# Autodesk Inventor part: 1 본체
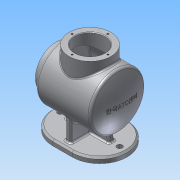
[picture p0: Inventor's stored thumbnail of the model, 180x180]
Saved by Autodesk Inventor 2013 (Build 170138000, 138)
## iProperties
Created: 2016-04
Part Number: 1 본체
Material: 알루미늄 6061
Document SubType Name: Modeling
Designer: Administrator
Mass: 911.528 g
Surface Area: 1226.33 cm^2
Volume: 336.357 cm^3
Density: 2.71 g/cm^3
Author: Administrator
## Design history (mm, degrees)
sketch "스케치1"
  geometry: L1 (-17.5, 50)-(17.5, 50); L2 (17.5, -50)-(-17.5, -50); A1 r 50 centre (17.5, 0) between (17.5, -50) and (17.5, 50); A2 r 50 centre (-17.5, 0) between (-17.5, 50) and (-17.5, -50); 2 further points
  constraints: 4 end point, 4 point on circle, 4 tangent, 2 centre point, 2 horizontal, 2 horizontal alignment, 1 midpoint, 1 vertical alignment
  dimensions: "d0" = 100 distance between parallel lines of L1 L2; "d2" = 135 dimension on A2 A1
extrude "돌출1" new body sketch "스케치1" distance "d3" = 10; taper "d4" = 0 deg
sketch "스케치3"
  geometry: L1 (67.5, 0)-(67.5, 10) reference; L2 (-67.5, 0)-(-67.5, 10) reference; L3 (-97.541, 79)-(111.394, 79); L4 (61.544, 79)-(61.544, 117); L5 (61.544, 117)-(49.544, 117); L6 (49.544, 117)-(49.544, 129); L7 (49.544, 129)-(-49.544, 129); A1 r 120 centre (59.544, 79) between (-49.544, 129) and (-60.456, 79); 2 further points
  constraints: 10 end point, 4 perpendicular, 3 point on line, 2 point on circle, 1 centre point, 1 midpoint, 1 parallel, 1 vertical alignment
  dimensions: "d19" = 79 vertical distance of L1.start L3.end; "d21" = 12 distance of L4.end L5.end; "d24" = 120 radius of A1; "d25" = 110 horizontal distance of L6.end A1.end; "d26" = 100 diameter of L7 L3; "d27" = 76 diameter of L5 L3
revolve "회전2" sketch "스케치3" stored, may be unused: angle "d28" = 90 deg
node "작업 평면1"
sketch "스케치9"
  geometry: C1 r 38 at (0, 0); 1 further point
  constraints: 1 centre point, 1 coincident
  dimensions: "d56" = 76 diameter of C1
extrude "돌출4" join sketch "스케치9" distance "d58" = 50; taper "d59" = 0 deg
sketch "스케치5"
  geometry: L1 (-49.544, 29)-(-49.544, 129) reference; L2 (49.544, 29)-(49.544, 129) reference; L3 (-17.5, 10)-(-67.5, 10) reference; L4 (67.5, 10)-(17.5, 10) reference; L5 (-29.773, 68)-(29.773, 68); L6 (29.773, 68)-(40, 10); L7 (-29.773, 68)-(-40, 10); L8 (17.5, 10)-(-17.5, 10) reference; 1 further point
  constraints: 6 end point, 2 point on line, 1 parallel
  dimensions: "d31" = 40 horizontal distance of point (0, 0) L6.end; "d32" = 80 distance of L6.end L7.end; "d33" = 100 deg angle of L4 L6; "d34" = 100 deg angle of L3 L7; "d35" = 58 distance between parallel lines of L4 L5
extrude "돌출2" join sketch "스케치5" stored distance "d36" = 10; taper "d37" = 0 deg
sketch "스케치7"
  geometry: L1 (50, 10)-(-50, 10) reference; L2 (-40, 49)-(-40, 10); L3 (-40, 49)-(40, 49); L4 (40, 49)-(40, 10); A1 r 50 centre (0, 79) between (-40, 49) and (40, 49) reference; 1 further point
  constraints: 6 end point, 3 perpendicular, 2 point on circle, 2 point on line
  dimensions: "d38" = 80 distance between parallel lines of L2 L4
extrude "돌출3" join sketch "스케치7" stored distance "d39" = 10; taper "d40" = 0 deg
node "작업 평면4"
sketch "스케치15"
  geometry: 2 further points
  constraints: 1 vertical alignment, 1 other
  dimensions: "d106" = 79 distance of point (0, 0) point (0, 79)
feature "엠보싱1" sketch "스케치15" dims "d0" = 100, "d2" = 135, "d107" = 0.5, "d108" = 0
sketch "스케치8"
  geometry: L1 (-49.544, 129)-(49.544, 129) reference; L2 (49.544, 117)-(61.544, 117) reference; L3 (61.544, 41)-(61.544, 117) reference; L4 (-46.286, 126)-(44.544, 126); L5 (46.544, 124)-(46.544, 79); L6 (61.544, 79)-(-60.456, 79); L7 (49.544, 29)-(49.544, 129) reference; A1 r 120 centre (59.544, 79) between (-49.544, 129) and (-49.544, 29) reference; A2 r 117 centre (59.544, 79) between (-48.127, 124.783) and (-57.456, 79); A3 r 2 centre (-46.286, 124) between (-46.286, 126) and (-48.127, 124.783); A4 r 2 centre (44.544, 124) between (46.544, 124) and (44.544, 126); 3 further points
  constraints: 8 point on circle, 6 end point, 5 point on line, 4 tangent, 3 centre point, 1 equal radius, 1 midpoint
  dimensions: "d41" = 3 radial gap between concentric circles of A1 A2; "d42" = 3 distance between parallel lines of L1 L4; "d44" = 3 distance between parallel lines of L7 L5; "d69" = 2 radius of A3
revolve "회전3" sketch "스케치8" stored, may be unused: angle "d45" = 90 deg
hole "구멍1" diameter "d48" = 54; stored, may be unused: countersink angle "d52" = 90 deg, drill point angle "d54" = 0 deg; dims "d46" = 10, "d47" = 10, "d49" = 6, "d50" = 4, "d51" = 2, "d53" = 20
hole "구멍2" diameter "d62" = 54; stored, may be unused: countersink angle "d66" = 90 deg, drill point angle "d68" = 0 deg; dims "d60" = 10, "d61" = 10, "d63" = 6, "d64" = 4, "d65" = 2, "d67" = 40
fillet "모깎기1" dims "d70" = 5
chamfer "모따기1" distance "d71" = 1; stored, may be unused: second distance "d72" = 2, angle "d73" = 45 deg
chamfer "모따기2" distance "d74" = 3; stored, may be unused: second distance "d75" = 2, angle "d76" = 45 deg
sketch "스케치10" dims "d77" = 65
  geometry: 3 further points
  constraints: 2 vertical alignment, 1 coincident, 2 other
hole "구멍3" sketch "스케치10" at (0, 32.5) diameter "d79" = 3.242; stored, may be unused: countersink angle "d83" = 90 deg, drill point angle "d85" = 118 deg; dims "d80" = 8, "d81" = 4, "d82" = 2, "d84" = 10
sketch "스케치11" dims "d89" = 65
  geometry: C1 r 38 at (0, 0) reference; 3 further points
  constraints: 2 vertical alignment, 1 coincident, 2 other
hole "구멍4" sketch "스케치11" at (0, 32.5) diameter "d91" = 3.242; stored, may be unused: countersink angle "d95" = 90 deg, drill point angle "d97" = 118 deg; dims "d92" = 8, "d93" = 4, "d94" = 2, "d96" = 10
fillet "모깎기2" dims "d102" = 3
fillet "모깎기3" dims "d103" = 3
fillet "모깎기4" dims "d109" = 3
sketch "스케치16"
  geometry: 3 further points
  constraints: 2 horizontal alignment
  dimensions: "d110" = 54 distance of point (54, 0) point (0, 0); "d111" = 54 distance of point (-54, 0) point (0, 0)
hole "구멍5" sketch "스케치16" at (-54, 0), (54, 0) diameter "d112" = 10; stored, may be unused: countersink angle "d116" = 90 deg, drill point angle "d118" = 118 deg; dims "d113" = 8, "d114" = 4, "d115" = 2, "d117" = 10
node "솔리드1"
pattern_circular "원형 패턴1" dims angle "d87" = 360 deg
pattern_circular "원형 패턴2" dims angle "d99" = 360 deg
other parameters: "d55" = 144, "d105" = 48
